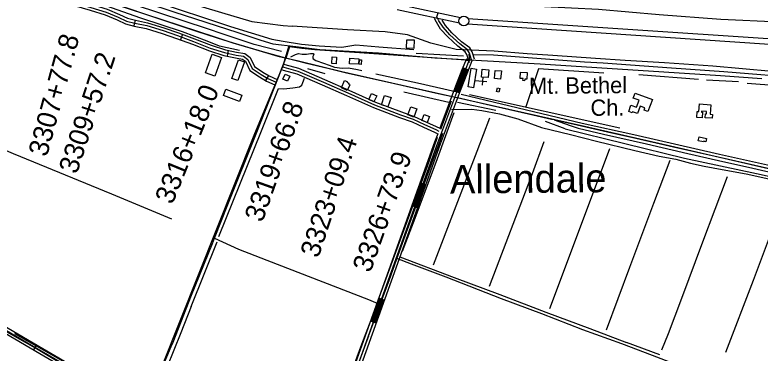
# Model space of a CAD drawing. Extents: x 3281947 to 3319794, y 715894 to 741249.
# Drawn here: x 3297609 to 3301406, y 724593 to 726318 of the extents above; entities that cross this region are included whole.
import ezdxf

# ---------------------------------------------------------------- set-up
doc = ezdxf.new("R2010")
doc.units = 0
for name, color, linetype in [('V-BLDG-OTLN', 7, 'Continuous'), ('V-DTCH-CNTR', 7, 'Continuous'), ('V-LEVE-TOET', 7, 'Continuous'), ('V-RAIL-TRAK', 7, 'Continuous'), ('V-ROAD-CNTR', 7, 'Continuous'), ('V-SITE-OTLN', 7, 'Continuous'), ('V-SITE-OTLN-IDEN', 7, 'Continuous'), ('V-SURV-IDEN', 7, 'Continuous'), ('V-SURV-LINE', 7, 'Continuous'), ('V-TOPO-GNAM-IDEN', 7, 'Continuous'), ('V-TOPO-SHOR', 7, 'Continuous')]:
    doc.layers.add(name, color=color, linetype=linetype)

msp = doc.modelspace()

# ---------------------------------------------------------------- linework, layer by layer
at = {"layer": 'V-BLDG-OTLN'}
for points in [[(3299603.4, 726150.1), (3299643.3, 726148.8), (3299644.6, 726188.8), (3299604.6, 726190.1)], [(3298580.4, 726023.1), (3298614.4, 726117.7), (3298661.9, 726100.6), (3298627.9, 726006)], [(3298779.1, 726078.8), (3298745.1, 725983.9), (3298714.7, 725994.8), (3298748.6, 726089.7)], [(3299246.8, 726102.7), (3299245.1, 726069.1), (3299223.9, 726070.2), (3299225.6, 726103.8)], [(3299360.7, 726095.1), (3299359.1, 726066.6), (3299313.2, 726069.1), (3299314.8, 726097.6)], [(3299362.7, 726066.6), (3299364.4, 726089.3), (3299375.8, 726088.5), (3299374.1, 726065.8)], [(3299008.9, 726006.5), (3298998, 725980.7), (3298974.5, 725990.6), (3298985.5, 726016.4)], [(3299946.6, 725947.2), (3299918.6, 725951.6), (3299933.4, 726046.1), (3299961.4, 726041.7)], [(3300023.3, 726038.8), (3300020.9, 725999.6), (3299987.1, 726001.6), (3299989.4, 726040.8)], [(3300052.1, 725993.5), (3300055.9, 726035.6), (3300088, 726032.6), (3300084.2, 725990.6)], [(3300217.3, 725989.8), (3300206.9, 725990.5), (3300206.3, 725982.4), (3300197.5, 725983), (3300198.2, 725993.2), (3300183.8, 725994.2), (3300185.9, 726026.1), (3300219.6, 726023.8)], [(3299302.6, 725933.1), (3299272.3, 725946.3), (3299289, 725984.5), (3299302.5, 725978.6), (3299300.8, 725974.7), (3299310.2, 725970.6), (3299307.9, 725965.2), (3299315.2, 725962)], [(3298671.7, 725907.7), (3298684.3, 725940.4), (3298765.4, 725909.2), (3298752.8, 725876.5)], [(3300074.5, 725924.5), (3300062.4, 725927.7), (3300067.5, 725946.9), (3300079.6, 725943.7)], [(3299411.9, 725886.8), (3299425.8, 725917.8), (3299452.4, 725905.9), (3299438.5, 725874.9)], [(3299526.1, 725896.5), (3299509.4, 725848.7), (3299476.3, 725860.3), (3299493, 725908.1)], [(3300857.2, 725887.7), (3300834.4, 725825.2), (3300815.4, 725832.1), (3300819.7, 725843.9), (3300794.7, 725853), (3300781.1, 725815.7), (3300756.2, 725824.8), (3300754.2, 725819.5), (3300736.7, 725825.8), (3300748.4, 725858), (3300776.7, 725847.8), (3300789.7, 725883.7), (3300760.2, 725894.4), (3300769.4, 725919.6)], [(3301094.3, 725825.2), (3301097.6, 725865), (3301155.9, 725860.3), (3301151.9, 725812.1), (3301163.1, 725811.2), (3301161.5, 725790.9), (3301125.9, 725793.8), (3301127.5, 725813.4), (3301132.8, 725813), (3301133.8, 725825.8), (3301108.5, 725827.9), (3301108.1, 725822.9), (3301112.8, 725822.5), (3301110.5, 725793.6), (3301083.6, 725795.8), (3301086, 725825.9)], [(3299626.8, 725850.3), (3299656.6, 725839.3), (3299641.1, 725797.6), (3299611.3, 725808.7)], [(3299694.9, 725810.4), (3299722, 725800.2), (3299710.3, 725769.3), (3299683.2, 725779.6)], [(3301133.5, 725688.4), (3301129.7, 725671.5), (3301119.1, 725673.8), (3301118.4, 725670.6), (3301091.1, 725676.7), (3301095.6, 725696.8)]]:
    msp.add_lwpolyline(points, close=True, dxfattribs=at)
at = {"layer": 'V-DTCH-CNTR'}
msp.add_line((3299410.4, 724679), (3299469.3, 724841.1), dxfattribs=at)
for points in [[(3299833.4, 725835.5), (3299938.1, 725836.8), (3299988.2, 725830.7), (3300078.9, 725814.2), (3300171.4, 725788.8), (3300292.4, 725744.5), (3300440, 725708.3), (3300572.1, 725674.3), (3300767.7, 725627.4), (3300892.3, 725597.7), (3300977, 725582.7), (3301051.8, 725562.5), (3301121.2, 725547.1), (3301213.2, 725529.4), (3301334.7, 725507.6), (3301511.4, 725469.3), (3301642.8, 725436.9), (3301737.7, 725414.5), (3301821.5, 725387.5)], [(3299469.3, 724841.1), (3299515.9, 724963.1), (3299555.4, 725074.6), (3299598.1, 725190.8), (3299691.6, 725446.9), (3299769, 725657.3), (3299790, 725715)], [(3298625.6, 725179.5), (3298748.5, 725124.2), (3298946, 725046.8), (3299410.5, 724866.3), (3299469.3, 724841.1)], [(3300088.6, 724870.9), (3299807.2, 724980), (3299629.3, 725047.3), (3299555.6, 725075.3)], [(3298264.4, 724283.4), (3298213.5, 724319.8), (3298046, 724418.3), (3297701.2, 724624.6), (3297330.4, 724834.9), (3297103.8, 724964.3)], [(3301662.9, 724677.2), (3301643.7, 724597.8), (3301625.2, 724525.2), (3301614.6, 724480), (3301582.9, 724339.6), (3301575.6, 724321.8), (3301570.1, 724317.6), (3301564, 724317.6), (3301510.5, 724339.7), (3301457, 724359.1), (3301401.5, 724381.2), (3301278.8, 724426), (3301150.6, 724474.2), (3301034.7, 724513.5), (3300857.9, 724580.5), (3300700.9, 724640.7), (3300502.8, 724711.6), (3300293.6, 724793.2), (3300088.6, 724870.9)], [(3299410.4, 724679), (3299395.7, 724638.7), (3299325.7, 724449.5), (3299265.4, 724291.8), (3299225.3, 724183.4)]]:
    msp.add_lwpolyline(points, dxfattribs=at)
at = {"layer": 'V-LEVE-TOET'}
for points in [[(3294339.3, 728953.2), (3294525.8, 728735.3), (3294820.4, 728397.9), (3295067, 728144.5), (3295142.1, 728077.2), (3295249.8, 727995.9), (3295501.2, 727821.5), (3295771, 727618.4), (3295991.4, 727449.3), (3296227.3, 727283.8), (3296424.9, 727134.4), (3296519.9, 727067.6), (3296613.5, 727019.5), (3296766.8, 726953.5), (3296839.1, 726924.5), (3296950.5, 726885.4), (3297245.6, 726780), (3297462.2, 726707.1), (3297806.4, 726592.9), (3298450, 726395.6), (3298661, 726330), (3298816.1, 726284.8), (3298975.8, 726263.9), (3299021.3, 726261.4)], [(3299992, 726391.5), (3300042.5, 726384.3), (3300307.2, 726361.6), (3300582.8, 726347.1), (3300892.2, 726319.8), (3301205.7, 726296.9), (3301503, 726283.2), (3301806.8, 726266.4), (3302178.7, 726237.7), (3302262.1, 726233.8), (3302384.5, 726248.4), (3302483, 726270.7), (3302708.2, 726330.7), (3302860.6, 726364.9), (3303048.3, 726402.8), (3303310.5, 726460.9), (3303535.9, 726508.4), (3303767.1, 726560.8), (3303976, 726613.9), (3304159.6, 726653.2), (3304362.8, 726699.7), (3304620, 726750.1), (3304769.2, 726802.3), (3304812.1, 726826.7)], [(3301468, 726029.1), (3301165.6, 726057.4), (3300918.5, 726073.3), (3300719.4, 726085.9), (3300566.9, 726096.2), (3300349.5, 726111.4), (3300219.9, 726120), (3300050.6, 726133.3), (3299858.2, 726142.5), (3299728.9, 726174.4), (3299610, 726217.4), (3299494.9, 726232.4), (3299303, 726242.2), (3299021.3, 726261.4)]]:
    msp.add_lwpolyline(points, dxfattribs=at)
at = {"layer": 'V-RAIL-TRAK'}
for points in [[(3298989.2, 726097.6), (3298883.4, 726126.9), (3298722.7, 726174.1), (3298641.5, 726199.8), (3298535.8, 726234.3), (3298438.2, 726266.4), (3298321.2, 726305.6), (3298134.7, 726367.5), (3297980.8, 726418.3), (3297809.2, 726475), (3297650.7, 726528), (3297483.5, 726583.4)], [(3299854.8, 725896.6), (3299750.9, 725919.5), (3299661.4, 725940.2), (3299520.5, 725972.5), (3299298.7, 726022), (3299204.1, 726044.6), (3299095.4, 726070.1), (3298989.2, 726097.6)], [(3300356.3, 725782.4), (3300342.6, 725785.4), (3300226.2, 725812.5), (3300032.4, 725856.1), (3299863.7, 725894.6), (3299854.8, 725896.6)], [(3300356.3, 725782.4), (3300438.3, 725754.2), (3300480, 725741.3), (3300609.1, 725709.8), (3300826.9, 725660.6), (3301038.1, 725611.4), (3301194.2, 725576.5), (3301370, 725536.1), (3301495.5, 725507.5), (3301644, 725473.3), (3301858.1, 725424.5), (3302091.1, 725371.2), (3302308.9, 725321.3), (3302526, 725272.3), (3302742.2, 725222.5), (3302960.9, 725173.3), (3303098.7, 725142.3), (3303287.3, 725099.6), (3303564.7, 725035.8)], [(3303567, 725051.6), (3303513.5, 725064), (3303288.4, 725115), (3302956, 725191), (3302842.2, 725216.2), (3302766.4, 725234), (3302611.9, 725269.2), (3302501, 725294), (3302383.6, 725321.2), (3302270.5, 725347), (3302077.4, 725390.7), (3301885.8, 725434.2), (3301438.6, 725536), (3301335.5, 725559.8), (3301193.3, 725592.3), (3300965.2, 725644.2), (3300773.2, 725688.5), (3300629.2, 725720.8), (3300474.6, 725756.5), (3300398.2, 725773.3), (3300356.3, 725782.4)]]:
    msp.add_lwpolyline(points, dxfattribs=at)
at = {"layer": 'V-ROAD-CNTR'}
for p, q in [((3298221.5, 726291.1), (3298214.1, 726262)), ((3298462.4, 726219.6), (3298451.8, 726191.5)), ((3298696.1, 726137.7), (3298689.7, 726108.4)), ((3299008.7, 726155.4), (3298989.2, 726097.6)), ((3298980.9, 726075.6), (3298989.2, 726097.6)), ((3299921.6, 726118.1), (3299925.2, 726086.7)), ((3298971, 726049.5), (3298980.9, 726075.6)), ((3299907.9, 726087.7), (3299925.2, 726086.7)), ((3299924.5, 726073.2), (3299925.2, 726086.7)), ((3299947.1, 726085.3), (3299925.2, 726086.7)), ((3299919.4, 726037.6), (3299891.5, 726048.6)), ((3298900.7, 726009.4), (3298885, 725983.9)), ((3299874.1, 725921.4), (3299846, 725931.9)), ((3299701.9, 725452.2), (3299673.7, 725462.3)), ((3299659.8, 725334.5), (3299631.6, 725344.6)), ((3299491.3, 724863.7), (3299463, 724873.8)), ((3299449.2, 724746.1), (3299420.9, 724756.2)), ((3297718.9, 724635.2), (3297703.8, 724609.3))]:
    msp.add_line(p, q, dxfattribs=at)
for points in [[(3297275.9, 726718), (3297644.1, 726594.2), (3297995.1, 726475.3), (3298419, 726334), (3298744.7, 726229.1), (3298861.7, 726189.3), (3298922.3, 726170.8), (3299040.1, 726157), (3299163.1, 726141.1), (3299461.9, 726124.1), (3299748, 726100), (3300285.2, 726068.1), (3301203.8, 726008.9), (3301415.7, 725994)], [(3297593.5, 726551.1), (3297846, 726465.9), (3298186, 726351.8), (3298626.7, 726207), (3298719.2, 726176.7), (3298835.4, 726142), (3298948.4, 726107.9), (3299054, 726084.9), (3299274.2, 726029.6), (3299620.3, 725952.3), (3299974.6, 725870.9), (3300512.2, 725750.1), (3300971.6, 725645.2), (3301493.7, 725524.7), (3301652.3, 725490)], [(3297557.2, 726507.4), (3297616.9, 726490.5), (3297685, 726463.5), (3297761.6, 726430.9), (3297813, 726406.3), (3297914.2, 726380.1), (3297996.2, 726357), (3298074.5, 726333.2), (3298135.3, 726307.2), (3298177.7, 726286.8), (3298219.3, 726276.1), (3298280.9, 726264), (3298363.7, 726238.2), (3298437.6, 726212.8), (3298518.2, 726182.6), (3298604.5, 726149.3), (3298677.5, 726126.4), (3298735.8, 726113.7), (3298774, 726107.6), (3298794.9, 726091.4), (3298818.1, 726045), (3298863.9, 726014.5), (3298897.8, 725993.6), (3298939.6, 725975.7)], [(3297560.6, 726522.1), (3297621.7, 726504.8), (3297690.7, 726477.4), (3297767.8, 726444.6), (3297818.2, 726420.4), (3297918.1, 726394.6), (3298000.4, 726371.4), (3298079.6, 726347.3), (3298141.5, 726320.9), (3298182.9, 726301), (3298222.6, 726290.8), (3298284.5, 726278.6), (3298368.4, 726252.5), (3298442.7, 726227), (3298523.6, 726196.6), (3298609.5, 726163.5), (3298681.3, 726140.9), (3298738.6, 726128.4), (3298780.2, 726121.8), (3298806.8, 726101.2), (3298829.7, 726055.3), (3298872, 726027.1), (3298904.7, 726007), (3298945.5, 725989.5)], [(3297553.7, 726492.8), (3297612.1, 726476.3), (3297679.3, 726449.6), (3297755.5, 726417.2), (3297807.8, 726392.1), (3297910.3, 726365.6), (3297991.9, 726342.6), (3298069.4, 726319), (3298129.1, 726293.5), (3298172.6, 726272.6), (3298216, 726261.5), (3298277.2, 726249.4), (3298359.1, 726223.9), (3298432.6, 726198.7), (3298512.9, 726168.6), (3298599.6, 726135.2), (3298673.6, 726111.9), (3298733.1, 726098.9), (3298767.9, 726093.4), (3298783, 726081.7), (3298806.4, 726034.7), (3298855.8, 726001.8), (3298890.9, 725980.3), (3298933.7, 725961.9)], [(3299936.1, 726088.8), (3299925.8, 726123.3), (3299915.2, 726141), (3299875.9, 726170.3), (3299825.4, 726216.7), (3299790.4, 726255.3), (3299769.8, 726288.8), (3299759.4, 726308.3), (3299765.3, 726329.8)], [(3299921.8, 726084.5), (3299912, 726117.2), (3299903.9, 726130.7), (3299866.3, 726158.7), (3299814.7, 726206.1), (3299778.3, 726246.3), (3299756.8, 726281.4), (3299746.9, 726299.8)], [(3299950.5, 726093.1), (3299939.6, 726129.5), (3299926.5, 726151.2), (3299885.4, 726181.9), (3299836, 726227.2), (3299802.4, 726264.3), (3299785.6, 726291.8)], [(3299005.3, 726161.1), (3298974, 726058), (3298825.7, 725703), (3298356.3, 724521.3), (3297978.4, 723584)], [(3299907.9, 726087.7), (3299340, 726127), (3299137.5, 726140.8), (3299070.8, 726147.3), (3299008.7, 726155.4)], [(3299923.8, 726089.6), (3299901, 726032), (3299863.6, 725936.1), (3299761.7, 725663.6), (3299511.6, 724964.9), (3299148.2, 723949.6), (3299122.2, 723876.9), (3299107.7, 723849.6), (3299098, 723835), (3299078.6, 723825), (3299065.5, 723827.2), (3299048.5, 723832.4), (3299003.8, 723860.3), (3298951.5, 723889.4), (3298913.2, 723905.8), (3298889.6, 723910.7), (3298870.1, 723903.7), (3298848.8, 723884.7), (3298831.4, 723856.2), (3298814, 723820.3), (3298730.5, 723575.4), (3298677.2, 723417.2), (3298650.5, 723323)], [(3299909.9, 726095.1), (3299887.1, 726037.5), (3299849.5, 725941.5), (3299779.8, 725754.8)], [(3299937.8, 726084), (3299915, 726026.5), (3299877.6, 725930.8), (3299775.8, 725658.5), (3299525.7, 724959.8), (3299162.3, 723944.6), (3299136, 723870.8), (3299120.6, 723841.9), (3299108.3, 723823.5), (3299081.1, 723809.3), (3299062, 723812.6), (3299042.2, 723818.6), (3298996.1, 723847.4), (3298944.8, 723875.9), (3298908.7, 723891.5), (3298890.7, 723895.2), (3298877.9, 723890.6), (3298860.4, 723875), (3298844.6, 723849), (3298827.9, 723814.6), (3298744.7, 723570.6), (3298691.5, 723412.7), (3298665, 723318.9)], [(3298972.5, 726054.4), (3298979.9, 726051.3), (3299049.7, 726031.9), (3299180.7, 725975.1), (3299304.7, 725921), (3299441.2, 725859.2), (3299573.2, 725809.3), (3299638, 725786.7), (3299696.6, 725759.5), (3299753.4, 725733.5), (3299769.4, 725725.1)], [(3298978.2, 726068.3), (3298984.8, 726065.5), (3299054.7, 726046.1), (3299186.7, 725988.9), (3299310.8, 725934.7), (3299447, 725873.1), (3299578.3, 725823.4), (3299643.7, 725800.6), (3299702.9, 725773.2), (3299774.4, 725740.3)], [(3298625.6, 725179.5), (3298693.9, 725351), (3298841.6, 725720.2), (3298952.7, 726001.2), (3298971, 726049.5)], [(3298966.7, 726040.6), (3298975, 726037.1), (3299044.7, 726017.8), (3299174.7, 725961.4), (3299298.6, 725907.3), (3299435.5, 725845.4), (3299568, 725795.2), (3299632.4, 725772.8), (3299690.3, 725745.9), (3299746.8, 725720), (3299763.5, 725711.2)], [(3299894.3, 726047.5), (3299889.9, 726036.4), (3299852.4, 725940.4), (3299848.8, 725930.8)], [(3299897.1, 726046.4), (3299892.7, 726035.3), (3299855.2, 725939.4), (3299851.6, 725929.8)], [(3299899.9, 726045.3), (3299895.5, 726034.2), (3299858, 725938.3), (3299854.4, 725928.7)], [(3299902.6, 726044.2), (3299898.3, 726033.1), (3299860.8, 725937.2), (3299857.2, 725927.7)], [(3299905.4, 726043.1), (3299901, 726032), (3299863.6, 725936.1), (3299860, 725926.6)], [(3299908.2, 726042), (3299903.8, 726030.9), (3299866.4, 725935.1), (3299862.8, 725925.6)], [(3299911, 726040.9), (3299906.6, 726029.8), (3299869.2, 725934), (3299865.6, 725924.5)], [(3299913.8, 726039.8), (3299909.4, 726028.7), (3299872, 725932.9), (3299868.4, 725923.5)], [(3299916.6, 726038.7), (3299912.2, 726027.6), (3299874.8, 725931.9), (3299871.2, 725922.4)], [(3299779.7, 725754.6), (3299774.1, 725739.5)], [(3299763.5, 725711.2), (3299747.6, 725668.8), (3299497.4, 724969.9), (3299134.1, 723954.7), (3299108.5, 723882.9), (3299094.8, 723857.3), (3299087.7, 723846.6), (3299076.2, 723840.6), (3299068.9, 723841.8), (3299054.7, 723846.1), (3299011.4, 723873.2), (3298958.1, 723902.8), (3298917.7, 723920.2), (3298888.5, 723926.2), (3298862.3, 723916.8), (3298837.1, 723894.4), (3298818.3, 723863.4), (3298800.1, 723826), (3298716.3, 723580.2), (3298662.9, 723421.6), (3298636.1, 723327)], [(3296173.7, 725522.6), (3296183.6, 725526.1), (3296215.9, 725522.3), (3296254.8, 725511.1), (3296305.5, 725486.7), (3296370.6, 725454.8), (3296418.5, 725433.6), (3296477.7, 725397.6), (3296543.9, 725357.3), (3296633, 725311.4), (3296700.4, 725273.2), (3296736.1, 725254.4), (3296764.9, 725224.3), (3296787.2, 725184.5), (3296802.8, 725164.8), (3296829.9, 725145.7), (3296894, 725111.6), (3297069.2, 725015.5), (3297395.5, 724824.3), (3297750.3, 724616.8), (3298093.5, 724416.6), (3298272.7, 724307.4)], [(3296160.9, 725486.2), (3296187, 725495.5), (3296210, 725492.8), (3296244.1, 725483), (3296292.4, 725459.7), (3296357.9, 725427.6), (3296404.6, 725406.9), (3296462.1, 725372), (3296529.2, 725331.1), (3296618.7, 725285), (3296686, 725246.9), (3296717.8, 725230.1), (3296740.6, 725206.3), (3296762.2, 725167.7), (3296782, 725142.8), (3296814.1, 725120.2), (3296879.7, 725085.2), (3297054.4, 724989.4), (3297380.4, 724798.4), (3297735.2, 724590.9), (3298078.1, 724390.8), (3298257.1, 724281.8)], [(3298264.9, 724294.6), (3298085.8, 724403.7), (3297742.8, 724603.9), (3297388, 724811.4), (3297061.8, 725002.5), (3296886.8, 725098.4), (3296822, 725133), (3296792.4, 725153.8), (3296774.7, 725176.1), (3296752.8, 725215.3), (3296727, 725242.3), (3296693.2, 725260), (3296625.9, 725298.2), (3296536.6, 725344.2), (3296469.9, 725384.8), (3296411.6, 725420.2), (3296364.2, 725441.2), (3296299, 725473.2), (3296249.5, 725497.1), (3296213, 725507.5), (3296185.3, 725510.8), (3296166.6, 725504.2)], [(3299676.5, 725461.3), (3299634.4, 725343.6)], [(3299679.3, 725460.3), (3299637.2, 725342.6)], [(3299682.2, 725459.2), (3299640, 725341.6)], [(3299685, 725458.2), (3299642.9, 725340.5)], [(3299687.8, 725457.2), (3299645.7, 725339.5)], [(3299690.6, 725456.2), (3299648.5, 725338.5)], [(3299693.5, 725455.2), (3299651.3, 725337.5)], [(3299696.3, 725454.2), (3299654.2, 725336.5)], [(3299699.1, 725453.2), (3299657, 725335.5)], [(3298414.5, 724649.7), (3298509.2, 724888), (3298615.1, 725152.9), (3298625.6, 725179.5)], [(3299465.9, 724872.8), (3299423.7, 724755.1)], [(3299468.7, 724871.8), (3299426.6, 724754.1)], [(3299471.5, 724870.8), (3299429.4, 724753.1)], [(3299474.3, 724869.8), (3299432.2, 724752.1)], [(3299477.2, 724868.8), (3299435, 724751.1)], [(3299480, 724867.8), (3299437.9, 724750.1)], [(3299482.8, 724866.8), (3299440.7, 724749.1)], [(3299485.6, 724865.8), (3299443.5, 724748.1)], [(3299488.5, 724864.7), (3299446.3, 724747.1)], [(3298361.6, 724522.4), (3298404.9, 724627.5), (3298414.5, 724649.7)]]:
    msp.add_lwpolyline(points, dxfattribs=at)
at = {"layer": 'V-SITE-OTLN'}
for p, q in [((3299953.2, 725984.2), (3300012.9, 725978)), ((3299990.9, 725960.2), (3299995, 726000))]:
    msp.add_line(p, q, dxfattribs=at)
at = {"layer": 'V-SURV-LINE'}
for points in [[(3299562.5, 726373.3), (3299880, 726305.8)], [(3299873.7, 726276.4), (3299556.2, 726344)], [(3299917.3, 726300.6), (3302288.7, 726141.7)], [(3302286.7, 726111.8), (3299915.3, 726270.6)]]:
    msp.add_lwpolyline(points, dxfattribs=at)
msp.add_circle((3299896.4, 726286.9), 25, dxfattribs=at)
at = {"layer": 'V-TOPO-SHOR'}
for p, q in [((3299654, 726123.1), (3299894, 726109.5)), ((3299190.2, 726017.1), (3299101.5, 726043.7)), ((3301091.9, 725988.2), (3300788.3, 726012.4)), ((3301296.1, 725976.6), (3301133.2, 725986.3)), ((3301737.1, 725939.1), (3301340.8, 725969.2)), ((3299819.5, 725871.8), (3299591.5, 725924.7)), ((3300498.9, 725765), (3299883, 725912.9)), ((3300692, 725740.2), (3299924.6, 725911.4)), ((3299779.6, 725735), (3299833.2, 725880.9)), ((3299864.4, 725873), (3300059.6, 725833.1)), ((3300412.1, 725737.8), (3300313.5, 725774.8)), ((3298507.3, 724831.2), (3298640.1, 725160.3)), ((3300895, 724584.5), (3300726.1, 724646.7))]:
    msp.add_line(p, q, dxfattribs=at)
for points in [[(3299946.3, 726116.7), (3300047.8, 726114.2), (3300512.2, 726079.1), (3300607, 726074.4), (3300954.2, 726048.4), (3301222.1, 726029.5), (3301640.6, 725996.3), (3301821.4, 725988.9), (3302132.8, 725967.1), (3302255.5, 725967), (3302368.1, 725979.1), (3302387, 725983.8), (3302495.1, 726000.3), (3302786.8, 726060.8), (3302913.7, 726093.2), (3303383.4, 726208.8), (3303450.2, 726227.2), (3304010.1, 726361.4), (3304604.7, 726485.9), (3304827.4, 726535.8), (3304890.7, 726560.9), (3304962.9, 726599.4), (3305132.7, 726700.2), (3305311.5, 726819.3)], [(3297581.5, 726638.4), (3297723.5, 726592.7), (3298125.1, 726459), (3298307.5, 726392.5), (3298708, 726258.8), (3298917.2, 726194.8), (3298976.4, 726184.1), (3299069.1, 726169.3), (3299158.4, 726161.2), (3299274.5, 726153.2), (3299346.9, 726166.1), (3299464.1, 726154.9), (3299641.6, 726141.9)], [(3298752.9, 726137.1), (3298651.5, 726159.4), (3298588.1, 726184.2), (3298462.3, 726232.6), (3298250.9, 726302.5), (3298042.7, 726374.4), (3297688.6, 726492.6), (3297578.7, 726530.6), (3297494.2, 726554.1)], [(3298967.9, 726131.1), (3298827.5, 726167.8), (3298670, 726220.2), (3298590.7, 726246.9), (3298222.9, 726368.1), (3298127.8, 726403.1), (3297693.4, 726546.9)], [(3299015.6, 726104.1), (3299038.7, 726116.9), (3299054.4, 726121.3), (3299072.4, 726118.3), (3299094.5, 726118.5), (3299114.5, 726121.8), (3299129.3, 726120.9), (3299132.5, 726115.6), (3299126.2, 726106.1), (3299126.3, 726098.7), (3299128.4, 726093.5), (3299142.2, 726086.2), (3299181.3, 726071.8), (3299209.9, 726061.5), (3299237.3, 726052.3), (3299276.4, 726047.3), (3299308, 726047.6), (3299354.4, 726039.6), (3299376.6, 726035.6)], [(3299448.4, 726018.3), (3299660.6, 725972.7), (3299853.8, 725928)], [(3300610.1, 726021.3), (3300277.1, 726043), (3300212.6, 725849.5)], [(3298648.3, 725187.8), (3298865, 725727.1), (3298951.6, 725942.8), (3298978.5, 725940.7), (3299024.9, 725945.8), (3299058.5, 725951.9), (3299071.1, 725959.9), (3299075.2, 725973.2), (3299084.5, 725995.9)], [(3299846.3, 725819.4), (3299759.9, 725583.6), (3299647.6, 725279.1), (3299582.7, 725111)], [(3299741.6, 725043.2), (3299964.1, 725623.9), (3300029.6, 725794.1)], [(3303136.5, 725167.5), (3302763.2, 725255), (3302475.2, 725318.7), (3302062.1, 725417.3), (3301741.8, 725488.3), (3301489.9, 725541), (3301200, 725606.5), (3300762.3, 725706.8), (3300498.9, 725765)], [(3300412.1, 725737.8), (3301020.5, 725588), (3301388, 725509.8), (3301503.6, 725484.4), (3301780.2, 725422.4), (3301986.9, 725365.6), (3302356.4, 725281.8), (3302714.4, 725211.1), (3302886.9, 725167.2), (3302907.7, 725163.6), (3303008, 725151.3)], [(3298408.1, 725276.6), (3298102.9, 725404.1), (3297601.1, 725610.1), (3297416.7, 725688)], [(3299460.5, 724863.9), (3299711.7, 725546.8), (3299763.1, 725694.8)], [(3300027.2, 724935.1), (3300246, 725508.6), (3300306.2, 725672.7)], [(3300335, 724821.3), (3300542.7, 725373.4), (3300639.8, 725637.7)], [(3300623.6, 724711.6), (3300742.8, 725031.8), (3300865, 725357.5), (3300948.2, 725576.8)], [(3301237.9, 725492.4), (3301112.3, 725159.3), (3301005.6, 724872.6), (3300937, 724691.7), (3300904.2, 724608)], [(3301232.4, 724598.6), (3301372.6, 724965.4), (3301469.3, 725223.8), (3301521.1, 725360.7)], [(3299569.8, 725085.2), (3299847.7, 724979.5), (3300079.3, 724892.9), (3300314.3, 724802.3), (3300538.1, 724718.9), (3300726.1, 724646.7)], [(3298507.3, 724831.2), (3298453.8, 724696.8), (3298382.8, 724519.3), (3298315.1, 724355.3), (3298303.4, 724324.4)], [(3299444.4, 724819.2), (3299374.9, 724637), (3299296.4, 724424), (3299229.2, 724241.3), (3299202.1, 724166.8), (3299176.2, 724095.7), (3299099, 723882.6), (3299091.3, 723863), (3299088.1, 723856.9), (3299085.7, 723853.6), (3299083.9, 723850.8), (3299079.3, 723847.5), (3299074.6, 723846), (3299067.6, 723845), (3299061.5, 723847.3), (3299049.8, 723852.8), (3298963, 723902.5), (3298864.5, 723958.2), (3298861.7, 723957.3), (3298859.4, 723954), (3298804.2, 723802.3), (3298722.7, 723592.9), (3298663.2, 723449.1), (3298656.8, 723437.4)], [(3298259.6, 724311.7), (3298198.4, 724347.8), (3298122.9, 724393.9), (3298051.5, 724435.4), (3297961.5, 724486.9), (3297852.6, 724552.3), (3297719, 724628.3), (3297607.8, 724691.2)]]:
    msp.add_lwpolyline(points, dxfattribs=at)

# ---------------------------------------------------------------- texts
at = {"layer": 'V-SITE-OTLN-IDEN'}
for s, p in [('Mt. Bethel', (3300229.2, 725915.1)), ('Ch.', (3300542.4, 725803.3))]:
    msp.add_text(s, height=83, rotation=0.4943, dxfattribs=at).set_placement(p)
at = {"layer": 'V-SURV-IDEN'}
for s, rotation, p in [('3307+77.8', 74.8242, (3297771.7, 725591)), ('3309+57.2', 71.7772, (3297924.1, 725502.4)), ('3316+18.0', 67.7754, (3298411.1, 725347.2)), ('3319+66.8', 70.4547, (3298869.7, 725256.2)), ('3323+09.4', 71.641, (3299155, 725074.3)), ('3326+73.9', 70.3987, (3299420.2, 724999.7))]:
    msp.add_text(s, height=100, rotation=rotation, dxfattribs=at).set_placement(p)
at = {"layer": 'V-TOPO-GNAM-IDEN'}
msp.add_text('Allendale', height=145, rotation=0.4943, dxfattribs=at).set_placement((3299826.4, 725407.3))

doc.saveas('drawing.dxf')
